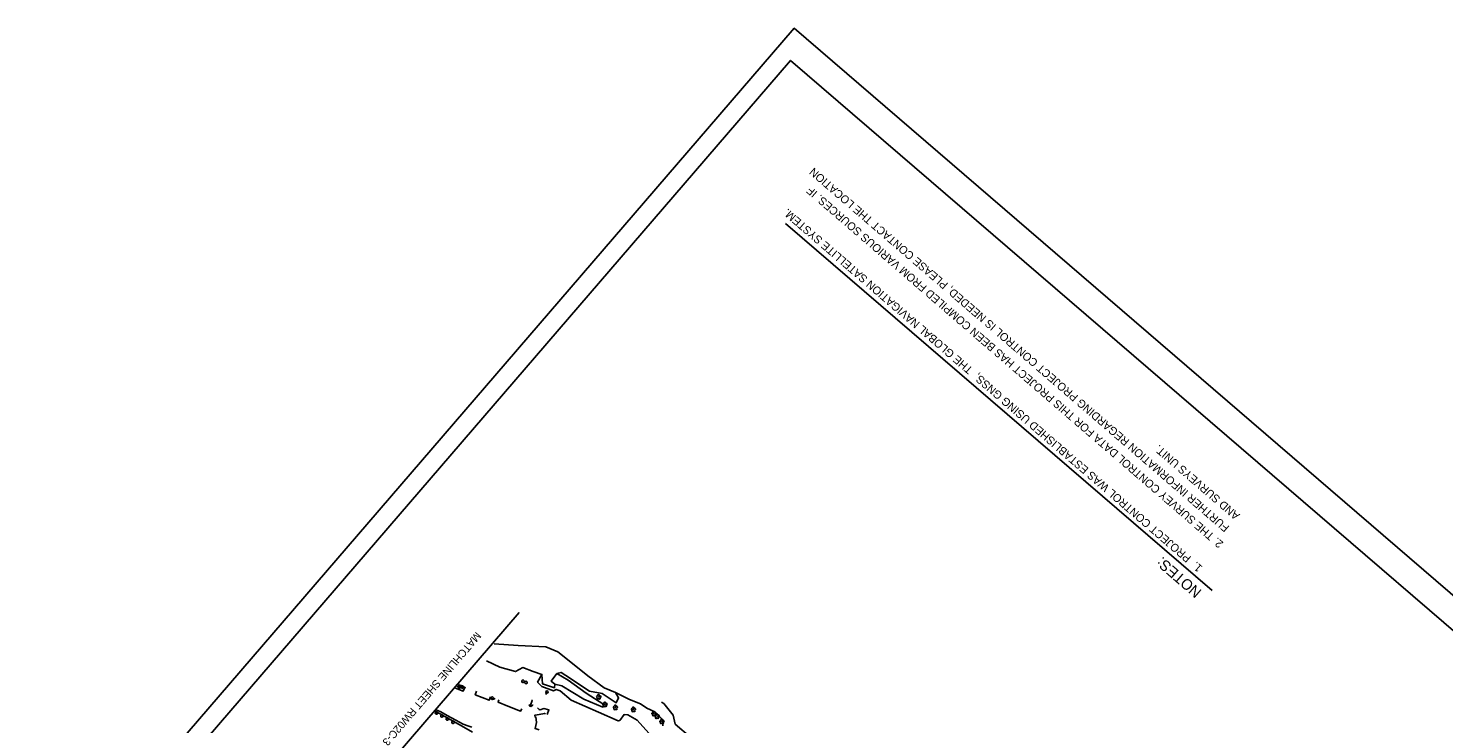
# Model space of a CAD drawing. Extents: x 478596 to 483012, y 490885 to 495165.
# Drawn here: x 478596 to 481533, y 493722 to 495165 of the extents above; entities that cross this region are included whole.
import ezdxf

# ---------------------------------------------------------------- set-up
doc = ezdxf.new("R2010")
doc.units = 0
for name, color, linetype in [('CTL Sheet Border CELL', 7, 'Continuous'), ('CTL Sheet Notes CELL', 7, 'Continuous'), ('Exist Other Culture Area Outline', 7, 'Continuous'), ('Exist Other Culture Fence Line', 7, 'Continuous'), ('Exist Roads Soil', 7, 'Continuous'), ('Exist Utilities Power Pole CELL', 7, 'Continuous'), ('Exist Vegetation Hedge Row', 7, 'Continuous'), ('Exist Vegetation Shrub CELL', 7, 'Continuous'), ('Exist Vegetation Tree CELL', 7, 'Continuous'), ('Exist Vegetation Woods Line', 7, 'Continuous'), ('Matchline', 7, 'Continuous'), ('Matchline Text', 7, 'Continuous'), ('Sheet Plot Border Outside CELL', 7, 'Continuous')]:
    doc.layers.add(name, color=color, linetype=linetype)

msp = doc.modelspace()

# ---------------------------------------------------------------- linework, layer by layer
at = {"layer": 'CTL Sheet Border CELL'}
msp.add_lwpolyline([(478660.7, 493335.7), (481178.4, 491168.5), (482695.4, 492930.9), (480177.7, 495098.1)], close=True, dxfattribs=at)
at = {"layer": 'CTL Sheet Notes CELL'}
msp.add_line((481052.1, 493997.6), (480166.8, 494759.6), dxfattribs=at)
msp.add_line((481052.1, 493997.6), (480166.8, 494759.6), dxfattribs=at)
at = {"layer": 'Exist Other Culture Area Outline'}
for points in [[(479526, 493789), (479523.4, 493781.6), (479552.4, 493770.2), (479555.2, 493777.6)], [(479636.4, 493760.8), (479638.1, 493760.2), (479641.5, 493769.5), (479640, 493770)], [(479648.5, 493739.4), (479646.8, 493739.1), (479647.5, 493735.3), (479649.1, 493735.5)], [(479656.1, 493708.7), (479647.6, 493711.3), (479650.8, 493724.3), (479649.1, 493735.5)], [(479648.5, 493739.4), (479666.8, 493742.8), (479669, 493741.9)]]:
    msp.add_lwpolyline(points, dxfattribs=at)
at = {"layer": 'Exist Other Culture Fence Line'}
msp.add_lwpolyline([(479517.7, 493704.2), (479494.8, 493716.8), (479471.4, 493730), (479449, 493742.6), (479438.1, 493748.4)], dxfattribs=at)
at = {"layer": 'Exist Roads Soil'}
for points in [[(479482.7, 493795.3), (479498.4, 493789.1), (479502.2, 493798.2)], [(479553.8, 493773.9), (479559, 493772.1), (479562.2, 493772.4), (479563.4, 493773.2), (479563.8, 493774.3)], [(479572.5, 493770.9), (479570.7, 493765.9), (479590.8, 493758.1), (479617.5, 493747.6), (479619.8, 493752.5)], [(479516.6, 493714.2), (479507.7, 493716.9), (479498.6, 493720.6), (479482.9, 493728.7), (479465.1, 493738.8), (479451.8, 493745.9), (479442, 493750.3)], [(479635.1, 493761.3), (479636.7, 493758), (479639, 493757.5), (479642.1, 493760), (479643.6, 493759.3)], [(479652.3, 493754.2), (479656.1, 493751), (479658.3, 493750.4), (479665.4, 493752.9), (479676.1, 493750.1), (479672.7, 493740.8)]]:
    msp.add_lwpolyline(points, dxfattribs=at)
at = {"layer": 'Exist Utilities Power Pole CELL'}
for q in [(479670, 493782.4), (479672, 493787.6)]:
    msp.add_line((479672, 493787.6), q, dxfattribs=at)
msp.add_circle((479672, 493787.6), 2.45, dxfattribs=at)
at = {"layer": 'Exist Vegetation Hedge Row'}
for points in [[(479883.8, 493701.8), (479859.2, 493728.7), (479840.2, 493739.7), (479832.3, 493740.4), (479823.2, 493728.3), (479820.2, 493727.2), (479779.2, 493745.2), (479722.7, 493770.1), (479699.7, 493789.9), (479691.4, 493792.8), (479685.5, 493789.8), (479661.5, 493798.8), (479652.6, 493807.9), (479661.6, 493823.7)], [(479688.8, 493803.7), (479702.9, 493800.3), (479748.7, 493772.1), (479788.2, 493755.9), (479790.1, 493761.2), (479753.7, 493785), (479715.9, 493812), (479692.7, 493825.7)], [(479814.3, 493786), (479843.6, 493771.4), (479866.1, 493762.9), (479879.4, 493754), (479895.7, 493746.3), (479912.3, 493729.7), (479912.8, 493716.9)]]:
    msp.add_lwpolyline(points, dxfattribs=at)
at = {"layer": 'Exist Vegetation Shrub CELL'}
for p, q in [((479487.7, 493801.3), (479487.7, 493801.3)), ((479490.4, 493797.7), (479490.4, 493797.7)), ((479493.3, 493798.3), (479493.3, 493798.3)), ((479496.6, 493797.4), (479496.6, 493797.4)), ((479622.4, 493809.3), (479622.4, 493809.3)), ((479628.8, 493806.9), (479628.8, 493806.9)), ((479558.4, 493774.4), (479558.4, 493774.4)), ((479443.1, 493743.7), (479443.1, 493743.7)), ((479454.3, 493737.3), (479454.3, 493737.3)), ((479465.7, 493731), (479465.7, 493731)), ((479477.2, 493724.4), (479477.2, 493724.4))]:
    msp.add_line(p, q, dxfattribs=at)
for centre, radius, start, end in [((479485.9, 493800.6), 0.955, 95.1099, 327.9534), ((479486.3, 493802.4), 0.968, 35.8908, 245.4216), ((479487.6, 493799.6), 0.984, 151.2797, 21.387), ((479488, 493803.3), 0.99, 334.8391, 200.4717), ((479488.6, 493797), 0.955, 95.1099, 327.9534), ((479488.9, 493798.8), 0.968, 35.8908, 245.4216), ((479489.4, 493800.4), 0.937, 204.9913, 73.4601), ((479489.4, 493802.2), 0.929, 284.4567, 126.0861), ((479490.3, 493796), 0.984, 151.2797, 21.387), ((479490.7, 493799.7), 0.99, 334.8391, 200.4717), ((479491.5, 493797.6), 0.955, 95.1099, 327.9534), ((479491.8, 493799.4), 0.968, 35.8908, 245.4216), ((479492.1, 493796.8), 0.937, 204.9913, 73.4601), ((479492.1, 493798.6), 0.929, 284.4567, 126.0861), ((479493.2, 493796.6), 0.984, 151.2797, 21.387), ((479493.5, 493800.4), 0.99, 334.8391, 200.4717), ((479494.8, 493796.7), 0.955, 95.1099, 327.9534), ((479495.1, 493798.5), 0.968, 35.8908, 245.4216), ((479494.9, 493797.4), 0.937, 204.9913, 73.4601), ((479495, 493799.2), 0.929, 284.4567, 126.0861), ((479496.4, 493795.7), 0.984, 151.2797, 21.387), ((479496.8, 493799.5), 0.99, 334.8391, 200.4717), ((479498.2, 493796.5), 0.937, 204.9913, 73.4601), ((479498.2, 493798.3), 0.929, 284.4567, 126.0861), ((479620.6, 493808.6), 0.955, 95.1099, 327.9534), ((479620.9, 493810.4), 0.968, 35.8908, 245.4216), ((479622.2, 493807.6), 0.984, 151.2797, 21.387), ((479622.6, 493811.4), 0.99, 334.8391, 200.4717), ((479624, 493808.4), 0.937, 204.9913, 73.4601), ((479624, 493810.2), 0.929, 284.4567, 126.0861), ((479627, 493806.2), 0.955, 95.1099, 327.9534), ((479627.3, 493808), 0.968, 35.8908, 245.4216), ((479628.7, 493805.2), 0.984, 151.2797, 21.387), ((479629, 493808.9), 0.99, 334.8391, 200.4717), ((479630.4, 493806), 0.937, 204.9913, 73.4601), ((479630.5, 493807.8), 0.929, 284.4567, 126.0861), ((479556.6, 493773.7), 0.955, 95.1099, 327.9534), ((479557, 493775.5), 0.968, 35.8908, 245.4216), ((479558.3, 493772.7), 0.984, 151.2797, 21.387), ((479558.7, 493776.4), 0.99, 334.8391, 200.4717), ((479560.1, 493773.5), 0.937, 204.9913, 73.4601), ((479560.1, 493775.3), 0.929, 284.4567, 126.0861), ((479441.3, 493743), 0.955, 95.1099, 327.9534), ((479441.6, 493744.8), 0.968, 35.8908, 245.4216), ((479443, 493742), 0.984, 151.2797, 21.387), ((479443.3, 493745.7), 0.99, 334.8391, 200.4717), ((479444.7, 493742.7), 0.937, 204.9913, 73.4601), ((479444.8, 493744.5), 0.929, 284.4567, 126.0861), ((479452.5, 493736.6), 0.955, 95.1099, 327.9534), ((479452.8, 493738.4), 0.968, 35.8908, 245.4216), ((479454.1, 493735.6), 0.984, 151.2797, 21.387), ((479454.5, 493739.3), 0.99, 334.8391, 200.4717), ((479455.9, 493736.4), 0.937, 204.9913, 73.4601), ((479455.9, 493738.2), 0.929, 284.4567, 126.0861), ((479463.9, 493730.3), 0.955, 95.1099, 327.9534), ((479464.2, 493732.1), 0.968, 35.8908, 245.4216), ((479465.5, 493729.3), 0.984, 151.2797, 21.387), ((479465.9, 493733), 0.99, 334.8391, 200.4717), ((479467.3, 493730), 0.937, 204.9913, 73.4601), ((479467.3, 493731.8), 0.929, 284.4567, 126.0861), ((479475.4, 493723.7), 0.955, 95.1099, 327.9534), ((479475.7, 493725.5), 0.968, 35.8908, 245.4216), ((479477.1, 493722.7), 0.984, 151.2797, 21.387), ((479477.4, 493726.4), 0.99, 334.8391, 200.4717), ((479478.8, 493723.5), 0.937, 204.9913, 73.4601), ((479478.9, 493725.3), 0.929, 284.4567, 126.0861)]:
    msp.add_arc(centre, radius, start, end, dxfattribs=at)
at = {"layer": 'Exist Vegetation Tree CELL'}
for p, q in [((479779.6, 493777.2), (479779.6, 493777.2)), ((479792.4, 493761.7), (479792.4, 493761.7)), ((479814.2, 493755.3), (479814.2, 493755.3)), ((479851.7, 493751.1), (479851.7, 493751.1)), ((479894.1, 493742.7), (479894.1, 493742.7)), ((479900.6, 493737.1), (479900.6, 493737.1)), ((479910.7, 493726.4), (479910.7, 493726.4))]:
    msp.add_line(p, q, dxfattribs=at)
for centre in [(479779.6, 493777.2), (479792.4, 493761.7), (479814.2, 493755.3), (479851.7, 493751.1), (479894.1, 493742.7), (479900.6, 493737.1), (479910.7, 493726.4)]:
    msp.add_circle(centre, 0.326, dxfattribs=at)
for centre, radius, start, end in [((479776.9, 493777.3), 1.73, 62.6636, 279.3457), ((479777.8, 493774), 1.69, 111.5671, 6.231), ((479779.2, 493780), 1.86, 330.1651, 219.7134), ((479781.2, 493774.3), 1.7, 181.2822, 74.56), ((479782.1, 493777.7), 1.9, 257.1011, 134.1999), ((479792, 493764.5), 1.86, 330.1651, 219.7134), ((479795, 493762.2), 1.9, 257.1011, 134.1999), ((479789.8, 493761.8), 1.73, 62.6636, 279.3457), ((479790.7, 493758.5), 1.69, 111.5671, 6.231), ((479794.1, 493758.8), 1.7, 181.2822, 74.56), ((479811.6, 493755.4), 1.73, 62.6636, 279.3457), ((479812.5, 493752.2), 1.69, 111.5671, 6.231), ((479813.8, 493758.2), 1.86, 330.1651, 219.7134), ((479815.9, 493752.4), 1.7, 181.2822, 74.56), ((479816.8, 493755.9), 1.9, 257.1011, 134.1999), ((479849.1, 493751.2), 1.73, 62.6636, 279.3457), ((479850, 493748), 1.69, 111.5671, 6.231), ((479851.3, 493754), 1.86, 330.1651, 219.7134), ((479853.3, 493748.2), 1.7, 181.2822, 74.56), ((479854.2, 493751.7), 1.9, 257.1011, 134.1999), ((479891.5, 493742.8), 1.73, 62.6636, 279.3457), ((479892.4, 493739.5), 1.69, 111.5671, 6.231), ((479893.7, 493745.5), 1.86, 330.1651, 219.7134), ((479895.8, 493739.8), 1.7, 181.2822, 74.56), ((479896.6, 493743.3), 1.9, 257.1011, 134.1999), ((479898, 493737.3), 1.73, 62.6636, 279.3457), ((479898.9, 493734), 1.69, 111.5671, 6.231), ((479900.2, 493740), 1.86, 330.1651, 219.7134), ((479902.3, 493734.2), 1.7, 181.2822, 74.56), ((479903.2, 493737.7), 1.9, 257.1011, 134.1999), ((479908.1, 493726.5), 1.73, 62.6636, 279.3457), ((479909, 493723.3), 1.69, 111.5671, 6.231), ((479910.3, 493729.3), 1.86, 330.1651, 219.7134), ((479912.4, 493723.5), 1.7, 181.2822, 74.56), ((479913.2, 493727), 1.9, 257.1011, 134.1999)]:
    msp.add_arc(centre, radius, start, end, dxfattribs=at)
at = {"layer": 'Exist Vegetation Woods Line'}
for points in [[(479562.6, 493887.1), (479612.3, 493884)], [(479612.3, 493884), (479670, 493881), (479694.6, 493870.3), (479718.4, 493852.1), (479756.7, 493820.5), (479791.2, 493796), (479814.3, 493786), (479820.7, 493775.2), (479816, 493765), (479786.6, 493784), (479760.6, 493789), (479711.4, 493821.8), (479701.4, 493827.8), (479692.7, 493825.7), (479680.6, 493810), (479688.8, 493803.7), (479687.6, 493796.2), (479663.2, 493804.2), (479661.6, 493823.7), (479643.7, 493829.7), (479621.8, 493837.8), (479607, 493829.7), (479574.3, 493839)], [(479574.3, 493839), (479547, 493852)], [(480048, 493615.8), (480018.3, 493641.1), (479984.2, 493670.6), (479970.3, 493683.2), (479970.5, 493692.9), (479938.2, 493720.7), (479933.8, 493739.1), (479914.5, 493763.6), (479909.9, 493766)]]:
    msp.add_lwpolyline(points, dxfattribs=at)
at = {"layer": 'Matchline'}
msp.add_line((479288.4, 493573.4), (479614.6, 493952.4), dxfattribs=at)
at = {"layer": 'Sheet Plot Border Outside CELL'}
msp.add_lwpolyline([(483011.9, 492731.6), (480185.3, 495164.6), (478596, 493318.3), (481422.6, 490885.3)], close=True, dxfattribs=at)

# ---------------------------------------------------------------- texts
at = {"layer": 'CTL Sheet Notes CELL'}
for s, height, p in [('  FURTHER INFORMATION REGARDING PROJECT CONTROL IS NEEDED, PLEASE CONTACT THE LOCATION', 16.606, (481098.6, 494122.3)), ('  FURTHER INFORMATION REGARDING PROJECT CONTROL IS NEEDED, PLEASE CONTACT THE LOCATION', 16.606, (481098.6, 494122.3)), ('2. THE SURVEY CONTROL DATA FOR THIS PROJECT HAS BEEN COMPILED FROM VARIOUS SOURCES. IF', 16.606, (481076.9, 494097.1)), ('2. THE SURVEY CONTROL DATA FOR THIS PROJECT HAS BEEN COMPILED FROM VARIOUS SOURCES. IF', 16.606, (481076.9, 494097.1)), ('1.  PROJECT CONTROL WAS ESTABLISHED USING GNSS,  THE GLOBAL NAVIGATION SATELLITE SYSTEM.', 16.606, (481033.5, 494046.9)), ('1.  PROJECT CONTROL WAS ESTABLISHED USING GNSS,  THE GLOBAL NAVIGATION SATELLITE SYSTEM.', 16.606, (481033.5, 494046.9)), ('  AND SURVEYS UNIT. ', 16.606, (481120.3, 494147.4)), ('  AND SURVEYS UNIT. ', 16.606, (481120.3, 494147.4)), ('NOTES:', 22.15, (481032.1, 493997.4)), ('NOTES:', 22.15, (481032.1, 493997.4))]:
    msp.add_text(s, height=height, rotation=139.1742, dxfattribs=at).set_placement(p)
at = {"layer": 'Matchline Text'}
msp.add_text('MATCHLINE SHEET RW02C-3', height=16, rotation=229.5222, dxfattribs=at).set_placement((479525, 493913.3))

doc.saveas('drawing.dxf')
